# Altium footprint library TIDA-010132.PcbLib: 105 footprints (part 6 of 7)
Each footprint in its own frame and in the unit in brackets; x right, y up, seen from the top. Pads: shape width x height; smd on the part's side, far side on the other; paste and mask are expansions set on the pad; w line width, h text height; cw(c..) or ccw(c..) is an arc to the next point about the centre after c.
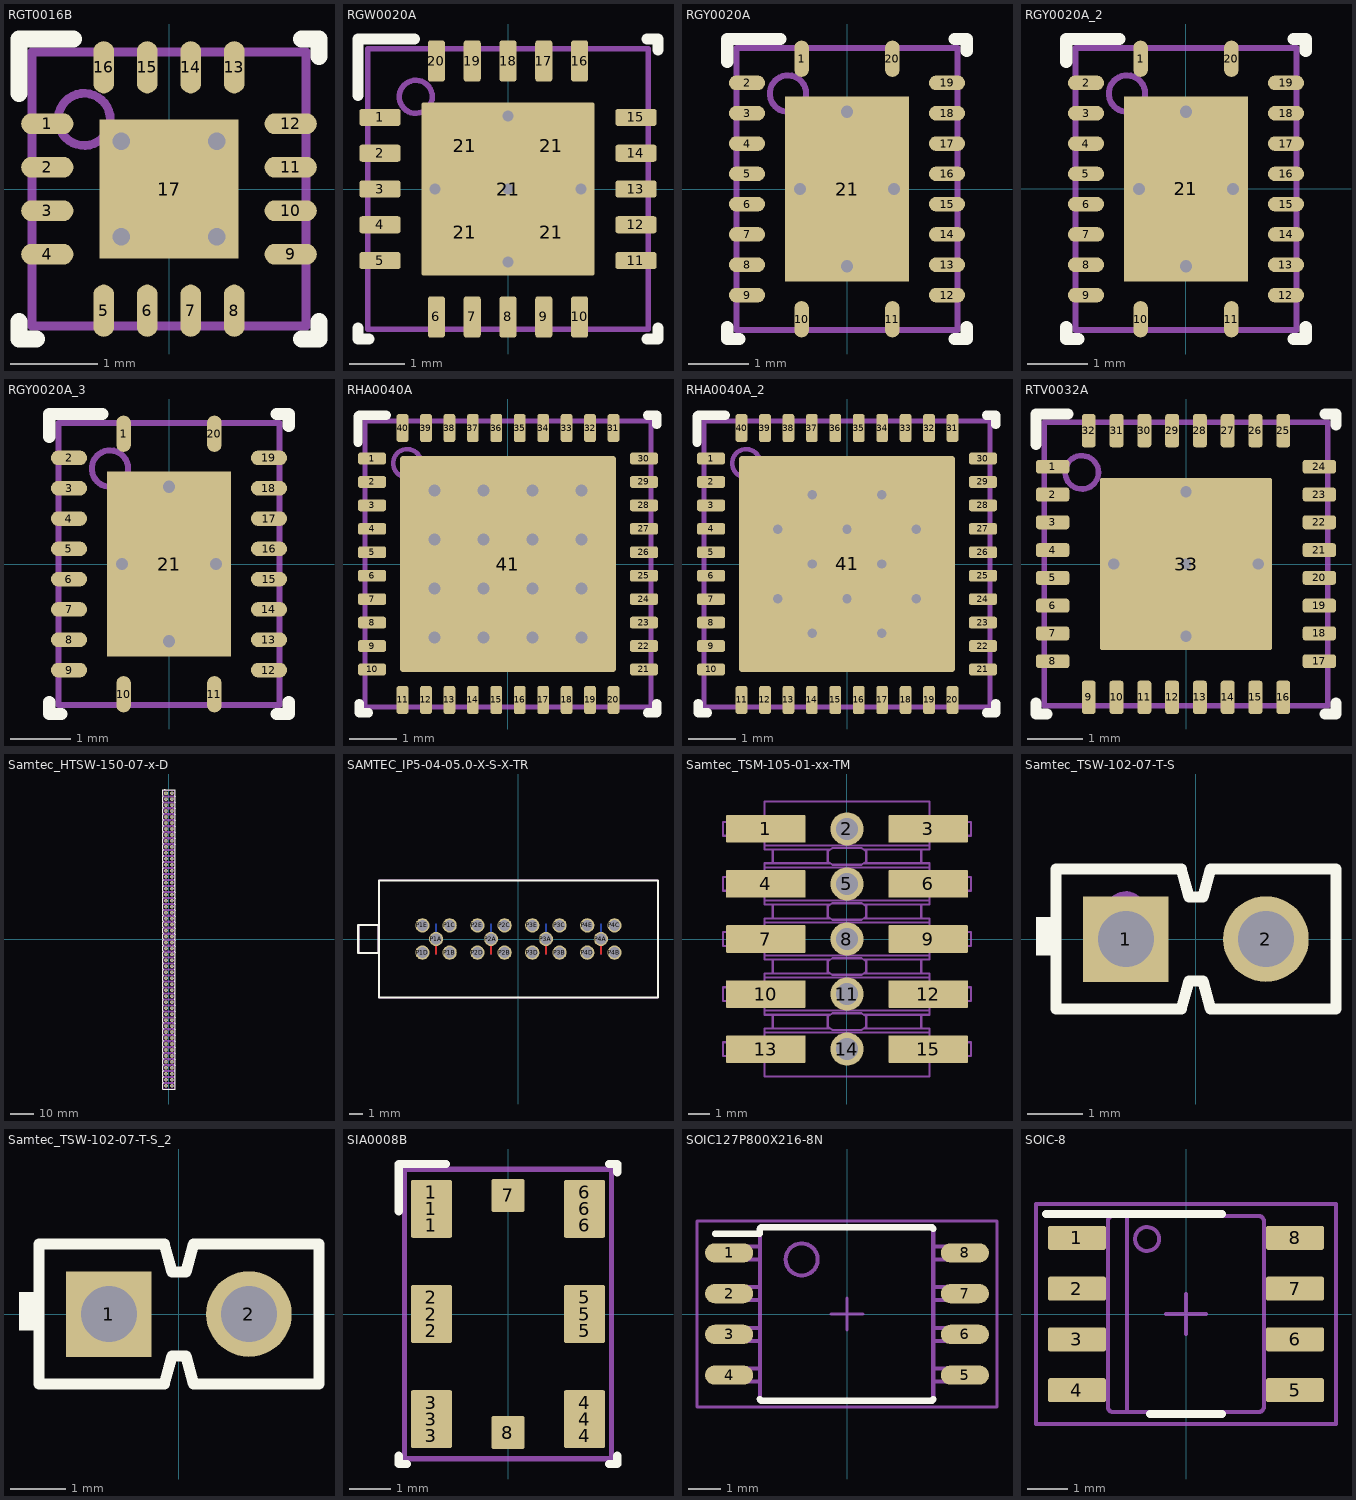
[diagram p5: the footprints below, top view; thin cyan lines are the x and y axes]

## RGT0016B [mm] "QFN, 16-Leads, Body 3x3mm, Pitch 0.5mm, Thermal Pad 1.6x1.6mm, TI Recommended"
height 1
pads (17):
  oval 0.6x0.24 smd: 1(-1.4,0.75) 2(-1.4,0.25) 3(-1.4,-0.25) 4(-1.4,-0.75) 9(1.4,-0.75) 10(1.4,-0.25) 11(1.4,0.25) 12(1.4,0.75)
  oval 0.24x0.6 smd: 5(-0.75,-1.4) 6(-0.25,-1.4) 7(0.25,-1.4) 8(0.75,-1.4) 13(0.75,1.4) 14(0.25,1.4) 15(-0.25,1.4) 16(-0.75,1.4)
  rect 1.6x1.6 smd paste-0.8: 17(0,0)
via 0.55,0.55 diameter 0.5 hole 0.2
via -0.55,-0.55 diameter 0.5 hole 0.2
via 0.55,-0.55 diameter 0.5 hole 0.2
via -0.55,0.55 diameter 0.5 hole 0.2
Top Overlay:
  lines w0.2: -1.725,-1.525 -1.725,-1.725 -1.525,-1.725 ; -1.725,1.1 -1.725,1.725 -1.1,1.725 ; 1.525,-1.725 1.725,-1.725 1.725,-1.525 ; 1.525,1.725 1.725,1.725 1.725,1.525
Top Paste:
  rectangle: -0.733,-0.733 0.733,0.733
Mechanical 5:
  circle w0.1: c-0.975,0.8 r0.3
  lines w0.1: -1.575,-1.575 -1.575,1.575 1.575,1.575 1.575,-1.575 -1.575,-1.575
  text ".Designator" at -1.397,-1.143 h0.46
3D body: height 1, standoff 0, extent -1.575,-1.575 1.575,1.575
3D body: height 1.01, standoff 0.5, extent -1.274,0.501 -0.676,1.099

## RGW0020A [mm] "QFN, 20-Leads, Body 5x5mm, Pitch 0.65mm, Thermal Pad 3.15x3.15mm, TI Recommended"
height 1
pads (25):
  rrect32% 0.75x0.31 smd: 1(-2.325,1.3) 2(-2.325,0.65) 3(-2.325,0) 4(-2.325,-0.65) 5(-2.325,-1.3) 11(2.325,-1.3) 12(2.325,-0.65) 13(2.325,0) 14(2.325,0.65) 15(2.325,1.3)
  rrect32% 0.31x0.75 smd: 6(-1.3,-2.325) 7(-0.65,-2.325) 8(0,-2.325) 9(0.65,-2.325) 10(1.3,-2.325) 16(1.3,2.325) 17(0.65,2.325) 18(0,2.325) 19(-0.65,2.325) 20(-1.3,2.325)
  rrect50% 1.37x1.37 on Top Paste: 21(-0.785,-0.785) 21(-0.785,0.785) 21(0.785,-0.785) 21(0.785,0.785)
  rrect3% 3.15x3.15 smd paste-1.575: 21(0,0)
via 0,1.325 diameter 0.5 hole 0.2
via -1.325,0 diameter 0.5 hole 0.2
via 0,0 diameter 0.5 hole 0.2
via 1.325,0 diameter 0.5 hole 0.2
via 0,-1.325 diameter 0.5 hole 0.2
Top Overlay:
  lines w0.2: -2.725,-2.525 -2.725,-2.725 -2.525,-2.725 ; -2.725,1.7 -2.725,2.725 -1.7,2.725 ; 2.525,-2.725 2.725,-2.725 2.725,-2.525 ; 2.525,2.725 2.725,2.725 2.725,2.525
Mechanical 5:
  circle w0.1: c-1.675,1.675 r0.3
  lines w0.1: -2.55,-2.55 2.55,-2.55 2.55,2.55 -2.55,2.55 -2.55,-2.55
  text ".Designator" at -1.854,-0.508 h0.46
3D body: height 1, standoff 0, extent -2.549,-2.549 2.549,2.549
3D body: height 1.01, standoff 0.5, extent -1.974,1.376 -1.376,1.974

## RGY0020A [mm] "QFN, 20-Leads, Body 4.5x3.5mm, Pitch 0.5mm, Thermal Pad 3.05x2.05mm, TI Recommended"
height 1
pads (21):
  oval 0.24x0.6 smd: 1(-0.75,2.15) 10(-0.75,-2.15) 11(0.75,-2.15) 20(0.75,2.15)
  oval 0.6x0.24 smd: 2(-1.65,1.75) 3(-1.65,1.25) 4(-1.65,0.75) 5(-1.65,0.25) 6(-1.65,-0.25) 7(-1.65,-0.75) 8(-1.65,-1.25) 9(-1.65,-1.75) 12(1.65,-1.75) 13(1.65,-1.25) 14(1.65,-0.75) 15(1.65,-0.25) 16(1.65,0.25) 17(1.65,0.75) 18(1.65,1.25) 19(1.65,1.75)
  rect 2.05x3.05 smd paste-1.025: 21(0,0)
via 0,1.275 diameter 0.5 hole 0.2
via -0.775,0 diameter 0.5 hole 0.2
via 0,-1.275 diameter 0.5 hole 0.2
via 0.775,0 diameter 0.5 hole 0.2
Top Overlay:
  lines w0.2: -1.975,-2.275 -1.975,-2.475 -1.775,-2.475 ; -1.975,2.1 -1.975,2.475 -1.1,2.475 ; 1.775,-2.475 1.975,-2.475 1.975,-2.275 ; 1.775,2.475 1.975,2.475 1.975,2.275
Top Paste:
  rectangle: 0.1,0.1 1.017,1.428
  region: -0.1,1.428 -1.017,1.428 -1.017,0.1 -0.1,0.1
  region: -0.1,-0.1 -1.017,-0.1 -1.017,-1.428 -0.1,-1.428
  rectangle: 0.1,-1.428 1.017,-0.1
Mechanical 5:
  circle w0.1: c-0.975,1.575 r0.3
  lines w0.1: -1.825,-2.325 1.825,-2.325 1.825,2.325 -1.825,2.325 -1.825,-2.325
  text ".Designator" at -3.452,-0.953 h0.46
3D body "RGY0020A.stp": height 1, standoff 0, extent -1.75,-2.25 1.75,2.25

## RGY0020A_2 [mm]
pads (21):
  oval 0.24x0.6 smd: 1(-0.75,2.15) 10(-0.75,-2.15) 11(0.75,-2.15) 20(0.75,2.15)
  oval 0.6x0.24 smd: 2(-1.65,1.75) 3(-1.65,1.25) 4(-1.65,0.75) 5(-1.65,0.25) 6(-1.65,-0.25) 7(-1.65,-0.75) 8(-1.65,-1.25) 9(-1.65,-1.75) 12(1.65,-1.75) 13(1.65,-1.25) 14(1.65,-0.75) 15(1.65,-0.25) 16(1.65,0.25) 17(1.65,0.75) 18(1.65,1.25) 19(1.65,1.75)
  rect 2.05x3.05 smd paste-1.025: 21(0,0)
via 0,1.275 diameter 0.5 hole 0.2
via -0.775,0 diameter 0.5 hole 0.2
via 0,-1.275 diameter 0.5 hole 0.2
via 0.775,0 diameter 0.5 hole 0.2
Top Overlay:
  lines w0.2: -1.975,-2.275 -1.975,-2.475 -1.775,-2.475 ; -1.975,2.1 -1.975,2.475 -1.1,2.475 ; 1.775,-2.475 1.975,-2.475 1.975,-2.275 ; 1.775,2.475 1.975,2.475 1.975,2.275
Top Paste:
  rectangle: 0.1,0.1 1.017,1.428
  region: -0.1,1.428 -1.017,1.428 -1.017,0.1 -0.1,0.1
  region: -0.1,-0.1 -1.017,-0.1 -1.017,-1.428 -0.1,-1.428
  rectangle: 0.1,-1.428 1.017,-0.1
Mechanical 5:
  circle w0.1: c-0.975,1.575 r0.3
  lines w0.1: -1.825,-2.325 1.825,-2.325 1.825,2.325 -1.825,2.325 -1.825,-2.325
  text ".Designator" at -0.168,0.69 h0.46
3D body "RGY0020A.stp": height 1, standoff 0, extent -1.75,-2.25 1.75,2.25

## RGY0020A_3 [mm]
pads (21):
  oval 0.24x0.6 smd: 1(-0.75,2.15) 10(-0.75,-2.15) 11(0.75,-2.15) 20(0.75,2.15)
  oval 0.6x0.24 smd: 2(-1.65,1.75) 3(-1.65,1.25) 4(-1.65,0.75) 5(-1.65,0.25) 6(-1.65,-0.25) 7(-1.65,-0.75) 8(-1.65,-1.25) 9(-1.65,-1.75) 12(1.65,-1.75) 13(1.65,-1.25) 14(1.65,-0.75) 15(1.65,-0.25) 16(1.65,0.25) 17(1.65,0.75) 18(1.65,1.25) 19(1.65,1.75)
  rect 2.05x3.05 smd paste-1.025: 21(0,0)
via 0,1.275 diameter 0.5 hole 0.2
via -0.775,0 diameter 0.5 hole 0.2
via 0,-1.275 diameter 0.5 hole 0.2
via 0.775,0 diameter 0.5 hole 0.2
Top Overlay:
  lines w0.2: -1.975,-2.275 -1.975,-2.475 -1.775,-2.475 ; -1.975,2.1 -1.975,2.475 -1.1,2.475 ; 1.775,-2.475 1.975,-2.475 1.975,-2.275 ; 1.775,2.475 1.975,2.475 1.975,2.275
Top Paste:
  rectangle: 0.1,0.1 1.017,1.428
  region: -0.1,1.428 -1.017,1.428 -1.017,0.1 -0.1,0.1
  region: -0.1,-0.1 -1.017,-0.1 -1.017,-1.428 -0.1,-1.428
  rectangle: 0.1,-1.428 1.017,-0.1
Mechanical 5:
  circle w0.1: c-0.975,1.575 r0.3
  lines w0.1: -1.825,-2.325 1.825,-2.325 1.825,2.325 -1.825,2.325 -1.825,-2.325
  text ".Designator" at -1.397,-0.635 h0.46
3D body "RGY0020A.stp": height 1, standoff 0, extent -1.75,-2.25 1.75,2.25

## RHA0040A [mm] "QFN, 40-Leads, Body 6x6mm, Pitch 0.5mm, Thermal Pad 4.6x4.6mm, TI Recommended"
height 1
pads (41):
  rrect40% 0.6x0.25 smd: 1(-2.9,2.25) 2(-2.9,1.75) 3(-2.9,1.25) 4(-2.9,0.75) 5(-2.9,0.25) 6(-2.9,-0.25) 7(-2.9,-0.75) 8(-2.9,-1.25) 9(-2.9,-1.75) 10(-2.9,-2.25) 21(2.9,-2.25) 22(2.9,-1.75) 23(2.9,-1.25) 24(2.9,-0.75) 25(2.9,-0.25) 26(2.9,0.25) 27(2.9,0.75) 28(2.9,1.25) 29(2.9,1.75) 30(2.9,2.25)
  rrect40% 0.25x0.6 smd: 11(-2.25,-2.9) 12(-1.75,-2.9) 13(-1.25,-2.9) 14(-0.75,-2.9) 15(-0.25,-2.9) 16(0.25,-2.9) 17(0.75,-2.9) 18(1.25,-2.9) 19(1.75,-2.9) 20(2.25,-2.9) 31(2.25,2.9) 32(1.75,2.9) 33(1.25,2.9) 34(0.75,2.9) 35(0.25,2.9) 36(-0.25,2.9) 37(-0.75,2.9) 38(-1.25,2.9) 39(-1.75,2.9) 40(-2.25,2.9)
  rrect2% 4.6x4.6 smd paste-2.3: 41(0,0)
via -0.523,1.57 diameter 0.508 hole 0.254
via -1.57,0.523 diameter 0.508 hole 0.254
via -1.57,-1.57 diameter 0.508 hole 0.254
via -0.523,-1.57 diameter 0.508 hole 0.254
via 1.57,-1.57 diameter 0.508 hole 0.254
via 1.57,-0.523 diameter 0.508 hole 0.254
via 1.57,1.57 diameter 0.508 hole 0.254
via 1.57,0.523 diameter 0.508 hole 0.254
via -1.57,-0.523 diameter 0.508 hole 0.254
via -1.57,1.57 diameter 0.508 hole 0.254
via -0.523,0.523 diameter 0.508 hole 0.254
via 0.523,-1.57 diameter 0.508 hole 0.254
via 0.523,0.523 diameter 0.508 hole 0.254
via 0.523,1.57 diameter 0.508 hole 0.254
via -0.523,-0.523 diameter 0.508 hole 0.254
via 0.523,-0.523 diameter 0.508 hole 0.254
Top Overlay:
  lines w0.2: -3.2,2.6 -3.2,3.15 ; -3.175,-2.975 -3.175,-3.175 -2.975,-3.175 ; -3.175,3.175 -2.6,3.175 ; 2.975,-3.175 3.175,-3.175 3.175,-2.975 ; 2.975,3.175 3.175,3.175 3.175,2.975
Top Paste:
  region: -0.84,-0.84 -2.12,-0.84 -2.12,-2.12 -0.84,-2.12
  rectangle: 0.84,-2.12 2.12,-0.84
  rectangle: -0.64,-2.12 0.64,-0.84
  rectangle: -0.64,0.84 0.64,2.12
  rectangle: 0.84,0.84 2.12,2.12
  region: -0.84,2.12 -2.12,2.12 -2.12,0.84 -0.84,0.84
  region: -0.84,0.64 -2.12,0.64 -2.12,-0.64 -0.84,-0.64
  rectangle: 0.84,-0.64 2.12,0.64
  rectangle: -0.64,-0.64 0.64,0.64
Mechanical 5:
  circle w0.1: c-2.15,2.15 r0.3
  lines w0.1: -3.05,-3.05 -3.05,3.05 3.05,3.05 3.05,-3.05 -3.05,-3.05
  text ".Designator" at 0.457,-0.576 h0.46
3D body "RHA0040A.stp": height 1, standoff 0, extent -3,-3 3,3

## RHA0040A_2 [mm]
pads (41):
  rrect40% 0.6x0.25 smd: 1(-2.9,2.25) 2(-2.9,1.75) 3(-2.9,1.25) 4(-2.9,0.75) 5(-2.9,0.25) 6(-2.9,-0.25) 7(-2.9,-0.75) 8(-2.9,-1.25) 9(-2.9,-1.75) 10(-2.9,-2.25) 21(2.9,-2.25) 22(2.9,-1.75) 23(2.9,-1.25) 24(2.9,-0.75) 25(2.9,-0.25) 26(2.9,0.25) 27(2.9,0.75) 28(2.9,1.25) 29(2.9,1.75) 30(2.9,2.25)
  rrect40% 0.25x0.6 smd: 11(-2.25,-2.9) 12(-1.75,-2.9) 13(-1.25,-2.9) 14(-0.75,-2.9) 15(-0.25,-2.9) 16(0.25,-2.9) 17(0.75,-2.9) 18(1.25,-2.9) 19(1.75,-2.9) 20(2.25,-2.9) 31(2.25,2.9) 32(1.75,2.9) 33(1.25,2.9) 34(0.75,2.9) 35(0.25,2.9) 36(-0.25,2.9) 37(-0.75,2.9) 38(-1.25,2.9) 39(-1.75,2.9) 40(-2.25,2.9)
  rrect2% 4.6x4.6 smd paste-2.3: 41(0,0)
via 0,-0.74 diameter 0.5 hole 0.2
via -1.48,-0.74 diameter 0.5 hole 0.2
via -0.74,0 diameter 0.5 hole 0.2
via 1.48,-0.74 diameter 0.5 hole 0.2
via 0.74,1.48 diameter 0.5 hole 0.2
via 1.48,0.74 diameter 0.5 hole 0.2
via -1.48,0.74 diameter 0.5 hole 0.2
via 0.74,0 diameter 0.5 hole 0.2
via -0.74,1.48 diameter 0.5 hole 0.2
via 0.74,-1.48 diameter 0.5 hole 0.2
via -0.74,-1.48 diameter 0.5 hole 0.2
via 0,0.74 diameter 0.5 hole 0.2
Top Overlay:
  lines w0.2: -3.2,2.6 -3.2,3.15 ; -3.175,-2.975 -3.175,-3.175 -2.975,-3.175 ; -3.175,3.175 -2.6,3.175 ; 2.975,-3.175 3.175,-3.175 3.175,-2.975 ; 2.975,3.175 3.175,3.175 3.175,2.975
Top Paste:
  rectangle: -0.64,-0.64 0.64,0.64
  rectangle: 0.84,-0.64 2.12,0.64
  region: -0.84,0.64 -2.12,0.64 -2.12,-0.64 -0.84,-0.64
  region: -0.84,2.12 -2.12,2.12 -2.12,0.84 -0.84,0.84
  rectangle: 0.84,0.84 2.12,2.12
  rectangle: -0.64,0.84 0.64,2.12
  rectangle: -0.64,-2.12 0.64,-0.84
  rectangle: 0.84,-2.12 2.12,-0.84
  region: -0.84,-0.84 -2.12,-0.84 -2.12,-2.12 -0.84,-2.12
Mechanical 5:
  circle w0.1: c-2.15,2.15 r0.3
  lines w0.1: -3.05,-3.05 3.05,-3.05 3.05,3.05 -3.05,3.05 -3.05,-3.05
  text ".Designator" at -1.8,-0.5 h0.46
3D body "RHA0040A.stp": height 1, standoff 0, extent -3,-3 3,3

## RTV0032A [mm] "QFN, 32-Leads, Body 5x5mm, Pitch 0.5mm"
height 0.8
pads (33):
  rrect40% 0.6x0.25 smd: 1(-2.4,1.75) 2(-2.4,1.25) 3(-2.4,0.75) 4(-2.4,0.25) 5(-2.4,-0.25) 6(-2.4,-0.75) 7(-2.4,-1.25) 8(-2.4,-1.75) 17(2.4,-1.75) 18(2.4,-1.25) 19(2.4,-0.75) 20(2.4,-0.25) 21(2.4,0.25) 22(2.4,0.75) 23(2.4,1.25) 24(2.4,1.75)
  rrect40% 0.25x0.6 smd: 9(-1.75,-2.4) 10(-1.25,-2.4) 11(-0.75,-2.4) 12(-0.25,-2.4) 13(0.25,-2.4) 14(0.75,-2.4) 15(1.25,-2.4) 16(1.75,-2.4) 25(1.75,2.4) 26(1.25,2.4) 27(0.75,2.4) 28(0.25,2.4) 29(-0.25,2.4) 30(-0.75,2.4) 31(-1.25,2.4) 32(-1.75,2.4)
  rrect3% 3.1x3.1 smd paste-1.55: 33(0,0)
via 0,-1.3 diameter 0.5 hole 0.2
via 1.3,0 diameter 0.5 hole 0.2
via 0,0 diameter 0.5 hole 0.2
via -1.3,0 diameter 0.5 hole 0.2
via 0,1.3 diameter 0.5 hole 0.2
Top Overlay:
  lines w0.2: -2.7,-2.5 -2.7,-2.7 -2.5,-2.7 ; -2.7,2.15 -2.7,2.7 -2.125,2.7 ; 2.5,-2.7 2.7,-2.7 2.7,-2.5 ; 2.5,2.7 2.7,2.7 2.7,2.5
Top Paste:
  rectangle: 0.1,-1.4 1.4,-0.1
  region: -0.1,-0.1 -1.4,-0.1 -1.4,-1.4 -0.1,-1.4
  region: -0.1,1.4 -1.4,1.4 -1.4,0.1 -0.1,0.1
  rectangle: 0.1,0.1 1.4,1.4
Mechanical 5:
  circle w0.1: c-1.875,1.65 r0.3
  lines w0.1: -2.55,-2.55 2.55,-2.55 2.55,2.55 -2.55,2.55 -2.55,-2.55
  text ".Designator" at -1.524,-0.508 h0.46
3D body: height 0.8, standoff 0, extent -2.55,-2.55 2.55,2.55
3D body: height 0.81, standoff 0.5, extent -2.174,1.351 -1.576,1.949

## Samtec_HTSW-150-07-x-D [mm] "Header, 2.54mm, 50x2, Gold, TH"
height 8.71
pads (100):
  rrect50% 1.55x1.55 hole 1.02: 1(-1.27,62.23)
  round 1.55 hole 1.02: 2(1.27,62.23) 3(-1.27,59.69) 4(1.27,59.69) 5(-1.27,57.15) 6(1.27,57.15) 7(-1.27,54.61) 8(1.27,54.61) 9(-1.27,52.07) 10(1.27,52.07) 11(-1.27,49.53) 12(1.27,49.53) 13(-1.27,46.99) 14(1.27,46.99) 15(-1.27,44.45) 16(1.27,44.45) 17(-1.27,41.91) 18(1.27,41.91) 19(-1.27,39.37) 20(1.27,39.37) 21(-1.27,36.83) 22(1.27,36.83) 23(-1.27,34.29) 24(1.27,34.29) 25(-1.27,31.75) 26(1.27,31.75) 27(-1.27,29.21) 28(1.27,29.21) 29(-1.27,26.67) 30(1.27,26.67) 31(-1.27,24.13) 32(1.27,24.13) 33(-1.27,21.59) 34(1.27,21.59) 35(-1.27,19.05) 36(1.27,19.05) 37(-1.27,16.51) 38(1.27,16.51) 39(-1.27,13.97) 40(1.27,13.97) 41(-1.27,11.43) 42(1.27,11.43) 43(-1.27,8.89) 44(1.27,8.89) 45(-1.27,6.35) 46(1.27,6.35) 47(-1.27,3.81) 48(1.27,3.81) 49(-1.27,1.27) 50(1.27,1.27) 51(-1.27,-1.27) 52(1.27,-1.27) 53(-1.27,-3.81) 54(1.27,-3.81) 55(-1.27,-6.35) 56(1.27,-6.35) 57(-1.27,-8.89) 58(1.27,-8.89) 59(-1.27,-11.43) 60(1.27,-11.43) 61(-1.27,-13.97) 62(1.27,-13.97) 63(-1.27,-16.51) 64(1.27,-16.51) 65(-1.27,-19.05) 66(1.27,-19.05) 67(-1.27,-21.59) 68(1.27,-21.59) 69(-1.27,-24.13) 70(1.27,-24.13) 71(-1.27,-26.67) 72(1.27,-26.67) 73(-1.27,-29.21) 74(1.27,-29.21) 75(-1.27,-31.75) 76(1.27,-31.75) 77(-1.27,-34.29) 78(1.27,-34.29) 79(-1.27,-36.83) 80(1.27,-36.83) 81(-1.27,-39.37) 82(1.27,-39.37) 83(-1.27,-41.91) 84(1.27,-41.91) 85(-1.27,-44.45) 86(1.27,-44.45) 87(-1.27,-46.99) 88(1.27,-46.99) 89(-1.27,-49.53) 90(1.27,-49.53) 91(-1.27,-52.07) 92(1.27,-52.07) 93(-1.27,-54.61) 94(1.27,-54.61) 95(-1.27,-57.15) 96(1.27,-57.15) 97(-1.27,-59.69) 98(1.27,-59.69) 99(-1.27,-62.23) 100(1.27,-62.23)
Top Overlay:
  drawing of 495 lines, arcs and shapes, not listed
Mechanical 5:
  drawing of 2217 lines, arcs and shapes, not listed
  text ".Designator" at -1.4,-0.1 h0.46
3D body "HTSW-150-07-G-D.stp": height 8.38, standoff -2.54, extent -2.515,-63.5 2.515,63.5

## SAMTEC_IP5-04-05.0-X-S-X-TR [mil] "Plug, 4 Ports, TH"
height 361.1
pads (20):
  round 41 hole 31 mask+2: P1A(-236.25,0) P2A(-78.75,0) P3A(78.75,0) P4A(236.25,0)
  round 41 hole 31 mask+3: P1B(-197.25,-39) P1C(-197.25,39) P1D(-275.25,-39) P1E(-275.25,39) P2B(-39.75,-39) P2C(-39.75,39) P2D(-117.75,-39) P2E(-117.75,39) P3B(117.75,-39) P3C(117.75,39) P3D(39.75,-39) P3E(39.75,39) P4B(275.25,-39) P4C(275.25,39) P4D(197.25,-39) P4E(197.25,39)
Top Layer:
  region: 238.75,-44 233.75,-44 233.75,0 238.75,0
  region: 81.25,-44 76.25,-44 76.25,0 81.25,0
  region: -76.25,-44 -81.25,-44 -81.25,0 -76.25,0
  region: -233.75,-44 -238.75,-44 -238.75,0 -233.75,0
Bottom Layer:
  region: 238.75,-44 233.75,-44 233.75,44 238.75,44
  region: 81.25,-44 76.25,-44 76.25,44 81.25,44
  region: -76.25,-44 -81.25,-44 -81.25,44 -76.25,44
  region: -233.75,-44 -238.75,-44 -238.75,44 -233.75,44
Top Overlay:
  lines w6: -400,-40 -401.46,-40 ; -400,40 -401.46,40 ; -458.54,-40 -460,-40 -460,40 -458.54,40 ; -458.54,-40 -401.46,-40 ; -458.54,-40 -458.54,40 ; -458.54,40 -401.46,40 ; -401.46,-40 -401.46,40 ; -400,-168 400,-168 400,168 -330,168 -360,168 -390,168 -400,168 -400,45 -400,-45 -400,-168
Top Paste:
  drawing of 20 lines, arcs and shapes, not listed
Bottom Paste:
  drawing of 20 lines, arcs and shapes, not listed
Top Solder:
  region: 240.75,-46 231.75,-46 231.75,10 240.75,10
  region: 83.25,-46 74.25,-46 74.25,10 83.25,10
  region: -74.25,-46 -83.25,-46 -83.25,10 -74.25,10
  region: -231.75,-46 -240.75,-46 -240.75,10 -231.75,10
Bottom Solder:
  region: 240.75,-46 231.75,-46 231.75,46 240.75,46
  region: 83.25,-46 74.25,-46 74.25,46 83.25,46
  region: -74.25,-46 -83.25,-46 -83.25,46 -74.25,46
  region: -231.75,-46 -240.75,-46 -240.75,46 -231.75,46
Mechanical 5:
  lines w3.94: -400,-40 -401.46,-40 ; -400,40 -401.46,40 ; -458.54,-40 -458.54,40 ; -458.54,-40 -401.46,-40 ; -458.54,-40 -460,-40 -460,40 -458.54,40 ; -458.54,40 -401.46,40 ; -401.46,-40 -401.46,40 ; -400,-168 -400,-45 -400,45 -400,168 -390,168 -360,168 -330,168 400,168 400,-168 -400,-168
  text ".Designator" at -66.93,-19.68 h18
3D body "IP5-04-05.0-L-S-1-TR.stp": height 358.1, standoff -60, extent -460,-168 400,168
3D body: height 1000, standoff 0, extent 47.26,59.06 47.26,59.06

## Samtec_TSM-105-01-xx-TM [mm] "Header, 2.54mm, 5x3, SMT"
height 10.16
pads (15):
  rrect8% 3.68x1.27 smd: 1(-3.745,5.08) 3(3.745,5.08) 4(-3.745,2.54) 6(3.745,2.54) 7(-3.745,0) 9(3.745,0) 10(-3.745,-2.54) 12(3.745,-2.54) 13(-3.745,-5.08) 15(3.745,-5.08)
  round 1.53 hole 1.02: 2(0,5.08) 5(0,2.54) 8(0,0) 11(0,-2.54) 14(0,-5.08)
Mechanical 5:
  drawing of 238 lines, arcs and shapes, not listed
  text ".Designator" at -1.7,-0.5 h0.46
3D body "TSM-105-01-T-TM.stp": height 9.65, standoff -2.54, extent -5.715,-6.35 5.715,6.35

## Samtec_TSW-102-07-T-S [mm] "Header, 2.54 mm, 2x1, Tin, TH"
height 8.382
pads (2):
  rect 1.55x1.55 hole 1.02: 1(-1.27,0)
  round 1.55 hole 1.02: 2(1.27,0)
Top Overlay:
  rectangle: -2.9,-0.3 -2.54,0.4
  lines w0.2: -2.54,-1.27 -0.264,-1.27 -0.127,-0.762 0,-0.762 0.127,-0.762 0.264,-1.27 2.54,-1.27 2.54,1.27 0.264,1.27 0.127,0.762 0,0.762 -0.127,0.762 -0.264,1.27 -2.54,1.27 -2.54,-1.27
Mechanical 5:
  circle w0.152: c-1.27,0.508 r0.284
  lines w0.1: -2.54,-1.27 -2.54,1.27 -0.264,1.27 -0.127,0.762 0,0.762 0.127,0.762 0.264,1.27 2.54,1.27 2.54,-1.27 0.264,-1.27 0.127,-0.762 0,-0.762 -0.127,-0.762 -0.264,-1.27 -2.54,-1.27
  text ".Designator" at -2.1,-0.3 h0.46
3D body "Samtec-TSW-102-07-T-S.stp": height 8.38, standoff -2.54, extent -2.54,-1.27 2.54,1.27

## Samtec_TSW-102-07-T-S_2 [mm]
pads (2):
  rect 1.55x1.55 hole 1.02: 1(-1.27,0)
  round 1.55 hole 1.02: 2(1.27,0)
Top Overlay:
  rectangle: -2.9,-0.3 -2.54,0.4
  lines w0.2: -2.54,-1.27 -0.264,-1.27 -0.127,-0.762 0,-0.762 0.127,-0.762 0.264,-1.27 2.54,-1.27 2.54,1.27 0.264,1.27 0.127,0.762 0,0.762 -0.127,0.762 -0.264,1.27 -2.54,1.27 -2.54,-1.27
Mechanical 5:
  lines w0.1: -2.54,-1.27 -2.54,1.27 -0.264,1.27 -0.127,0.762 0,0.762 0.127,0.762 0.264,1.27 2.54,1.27 2.54,-1.27 0.264,-1.27 0.127,-0.762 0,-0.762 -0.127,-0.762 -0.264,-1.27 -2.54,-1.27
  text ".Designator" at -2.1,-0.3 h0.46
3D body "Samtec-TSW-102-07-T-S.stp": height 8.38, standoff -2.54, extent -2.54,-1.27 2.54,1.27

## SIA0008B [mm] "SIP 8-Leads, Body 5x7mm"
height 1.1
pads (20):
  rrect50% 1x0.6 on Top Paste: 1(-1.85,2.14) 1(-1.85,2.94) 2(-1.85,0.4) 2(-1.85,-0.4) 3(-1.85,-2.14) 3(-1.85,-2.94) 4(1.85,-2.94) 4(1.85,-2.14) 5(1.85,-0.4) 5(1.85,0.4) 6(1.85,2.94) 6(1.85,2.14)
  rrect10% 1x1.4 smd paste-0.5: 1(-1.85,2.54) 2(-1.85,0) 3(-1.85,-2.54) 4(1.85,-2.54) 5(1.85,0) 6(1.85,2.54)
  rrect12% 0.8x0.8 smd: 7(0,2.865) 8(0,-2.865)
Top Overlay:
  lines w0.2: -2.64,-3.425 -2.64,-3.625 -2.44,-3.625 ; -2.64,2.485 -2.64,3.625 -1.5,3.625 ; 2.44,-3.625 2.64,-3.625 2.64,-3.425 ; 2.44,3.625 2.64,3.625 2.64,3.425
Mechanical 5:
  circle w0.1: c-1.84,2.54 r0.25
  lines w0.127: -2.5,-3.5 -2.5,3.5 2.5,3.5 2.5,-3.5 -2.5,-3.5
  text ".Designator" at -1.4,0 h0.46
3D body: height 1.1, standoff 0, extent -2.564,-3.564 2.564,3.564
3D body: height 1.13, standoff 0, extent -2.156,2.224 -1.525,2.856

## SOIC127P800X216-8N [mm] "SOIC, 8-Leads, Body 5.3x5.3mm (max), Pitch 1.27mm, IPC Medium Density"
height 2.159
pads (8):
  oval 1.5x0.6 smd: 1(-3.675,1.905) 2(-3.675,0.635) 3(-3.675,-0.635) 4(-3.675,-1.905) 5(3.675,-1.905) 6(3.675,-0.635) 7(3.675,0.635) 8(3.675,1.905)
Top Overlay:
  lines w0.2: -4.113,2.505 -3.713,2.505 -3.573,2.505 -3.289,2.505 -2.963,2.505 -2.713,2.505 -2.713,2.65 cw(c-2.663,2.65) -2.663,2.7 -2.6,2.7 -2.159,2.7 2.508,2.7 2.637,2.7 cw(c2.637,2.65) 2.687,2.65 ; -2.713,-2.65 ccw(c-2.663,-2.65) -2.663,-2.7 -2.6,-2.7 -2.159,-2.7 2.508,-2.7 2.637,-2.7 ccw(c2.637,-2.65) 2.687,-2.65
Mechanical 5:
  lines w0.127: -2.713,-2.105 -2.963,-2.105 -3.289,-2.105 -3.573,-2.105 -3.713,-2.105 -4.113,-2.105 -4.113,-1.705 -3.713,-1.705 -3.573,-1.705 -3.289,-1.705 -2.963,-1.705 -2.713,-1.705 ; -2.713,-0.835 -2.963,-0.835 -3.289,-0.835 -3.573,-0.835 -3.713,-0.835 -4.113,-0.835 -4.113,-0.435 -3.713,-0.435 -3.573,-0.435 -3.289,-0.435 -2.963,-0.435 -2.713,-0.435 ; -2.713,0.435 -2.963,0.435 -3.289,0.435 -3.573,0.435 -3.713,0.435 -4.113,0.435 -4.113,0.835 -3.713,0.835 -3.573,0.835 -3.289,0.835 -2.963,0.835 -2.713,0.835 ; -2.713,1.705 -2.963,1.705 -3.289,1.705 -3.573,1.705 -3.713,1.705 -4.113,1.705 -4.113,2.105 -3.713,2.105 -3.573,2.105 -3.289,2.105 -2.963,2.105 -2.713,2.105 ; 2.687,-2.105 2.937,-2.105 3.263,-2.105 3.547,-2.105 3.687,-2.105 4.087,-2.105 4.087,-1.705 3.687,-1.705 3.547,-1.705 3.263,-1.705 2.937,-1.705 2.687,-1.705 ; 2.687,-0.835 2.937,-0.835 3.263,-0.835 3.547,-0.835 3.687,-0.835 4.087,-0.835 4.087,-0.435 3.687,-0.435 3.547,-0.435 3.263,-0.435 2.937,-0.435 2.687,-0.435 ; 2.687,0.435 2.937,0.435 3.263,0.435 3.547,0.435 3.687,0.435 4.087,0.435 4.087,0.835 3.687,0.835 3.547,0.835 3.263,0.835 2.937,0.835 2.687,0.835 ; 2.687,1.705 2.937,1.705 3.263,1.705 3.547,1.705 3.687,1.705 4.087,1.705 4.087,2.105 3.687,2.105 3.547,2.105 3.263,2.105 2.937,2.105 2.687,2.105 ; -2.713,-2.65 ccw(c-2.663,-2.65) -2.663,-2.7 -2.6,-2.7 -2.159,-2.7 2.508,-2.7 2.637,-2.7 ccw(c2.637,-2.65) 2.687,-2.65 2.687,2.65 ccw(c2.637,2.65) 2.637,2.7 2.508,2.7 -2.159,2.7 -2.6,2.7 -2.663,2.7 ccw(c-2.663,2.65) -2.713,2.65 -2.713,-2.65 ; -1.913,1.7 ccw(c-1.413,1.7) -0.913,1.7 ccw(c-1.413,1.7) -1.913,1.7
  text ".Designator" at -1.8,-0.4 h0.46
Mechanical 15:
  lines w0.1: -0.5,0 0.5,0 ; 0,-0.5 0,0.5 ; -4.675,-2.9 -4.675,2.9 4.675,2.9 4.675,-2.9 -4.675,-2.9
3D body "SOIC-8-208.stp": height 2.17, standoff 0.02, extent -4.1,-2.7 4.1,2.7

## SOIC-8 [mm] "duplicate of SO-8.  SOIC, 8-Leads, Body 5.0x4.0mm (max), Pitch 1.27mm, IPC Medium Density"
height 1.75
pads (8):
  rrect17% 1.45x0.6 smd: 1(-2.725,1.905) 2(-2.725,0.635) 3(-2.725,-0.635) 4(-2.725,-1.905) 5(2.725,-1.905) 6(2.725,-0.635) 7(2.725,0.635) 8(2.725,1.905)
Top Overlay:
  lines w0.2: -3.5,2.5 0.9,2.5 ; -0.9,-2.5 0.9,-2.5
Mechanical 5:
  circle w0.1: c-0.975,1.875 r0.3
  lines w0.1: -1.475,-2.45 -1.475,2.45 ; -2.375,-2.095 -1.995,-2.095 -1.952,-2.095 -1.952,-1.715 -1.995,-1.715 -2.375,-1.715 ; -2.375,-2.095 -2.589,-2.095 -3.002,-2.095 -3.002,-1.715 -2.589,-1.715 -2.375,-1.715 ; -2.375,-2.095 -2.375,-1.715 ; -2.375,-0.825 -1.995,-0.825 -1.952,-0.825 -1.952,-0.445 -1.995,-0.445 -2.375,-0.445 ; -2.375,-0.825 -2.589,-0.825 -3.002,-0.825 -3.002,-0.445 -2.589,-0.445 -2.375,-0.445 ; -2.375,-0.825 -2.375,-0.445 ; -2.375,0.445 -1.995,0.445 -1.952,0.445 -1.952,0.825 -1.995,0.825 -2.375,0.825 ; -2.375,0.445 -2.589,0.445 -3.002,0.445 -3.002,0.825 -2.589,0.825 -2.375,0.825 ; -2.375,0.445 -2.375,0.825 ; -2.375,1.715 -1.995,1.715 -1.952,1.715 -1.952,2.095 -1.995,2.095 -2.375,2.095 ; -2.375,1.715 -2.589,1.715 -3.002,1.715 -3.002,2.095 -2.589,2.095 -2.375,2.095 ; -2.375,1.715 -2.375,2.095 ; -0.332,-2.45 -1.825,-2.45 -1.826,-2.45 cw(c-1.825,-2.323) -1.952,-2.324 -1.952,-2.323 -1.952,2.323 -1.952,2.324 cw(c-1.825,2.323) -1.826,2.45 -1.825,2.45 -0.332,2.45 ; -0.332,-2.45 -0.182,-2.45 ; -0.332,-2.45 -0.182,-2.45 ; -0.332,2.45 -0.182,2.45 ; -0.332,2.45 -0.182,2.45 ; -0.182,-2.45 0.178,-2.45 ; -0.182,2.45 0.178,2.45 ; 0.178,-2.45 0.328,-2.45 ; 0.178,-2.45 0.328,-2.45 ; 0.178,2.45 0.328,2.45 ; 0.178,2.45 0.328,2.45 ; 0.328,-2.45 1.821,-2.45 1.822,-2.45 ccw(c1.821,-2.323) 1.948,-2.324 1.948,-2.323 1.948,2.323 1.948,2.324 ccw(c1.821,2.323) 1.822,2.45 1.821,2.45 0.328,2.45 ; 2.371,-2.095 2.585,-2.095 2.998,-2.095 2.998,-1.715 2.585,-1.715 2.371,-1.715 ; 2.371,-2.095 1.991,-2.095 1.948,-2.095 1.948,-1.715 1.991,-1.715 2.371,-1.715 ; 2.371,-2.095 2.371,-1.715 ; 2.371,-0.825 2.585,-0.825 2.998,-0.825 2.998,-0.445 2.585,-0.445 2.371,-0.445 ; 2.371,-0.825 1.991,-0.825 1.948,-0.825 1.948,-0.445 1.991,-0.445 2.371,-0.445 ; 2.371,-0.825 2.371,-0.445 ; 2.371,0.445 2.585,0.445 2.998,0.445 2.998,0.825 2.585,0.825 2.371,0.825 ; 2.371,0.445 1.991,0.445 1.948,0.445 1.948,0.825 1.991,0.825 2.371,0.825 ; 2.371,0.445 2.371,0.825 ; 2.371,1.715 2.585,1.715 2.998,1.715 2.998,2.095 2.585,2.095 2.371,2.095 ; 2.371,1.715 1.991,1.715 1.948,1.715 1.948,2.095 1.991,2.095 2.371,2.095 ; 2.371,1.715 2.371,2.095
  text ".Designator" at -0.623,4.545 h0.46
Mechanical 15:
  lines w0.1: -0.5,0 0.5,0 ; 0,-0.5 0,0.5 ; -3.75,-2.75 3.75,-2.75 3.75,2.75 -3.75,2.75 -3.75,-2.75
3D body "SOIC-8akaD0008AakaM08A.stp": height 1.63, standoff 0, extent -3,-2.45 3,2.45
